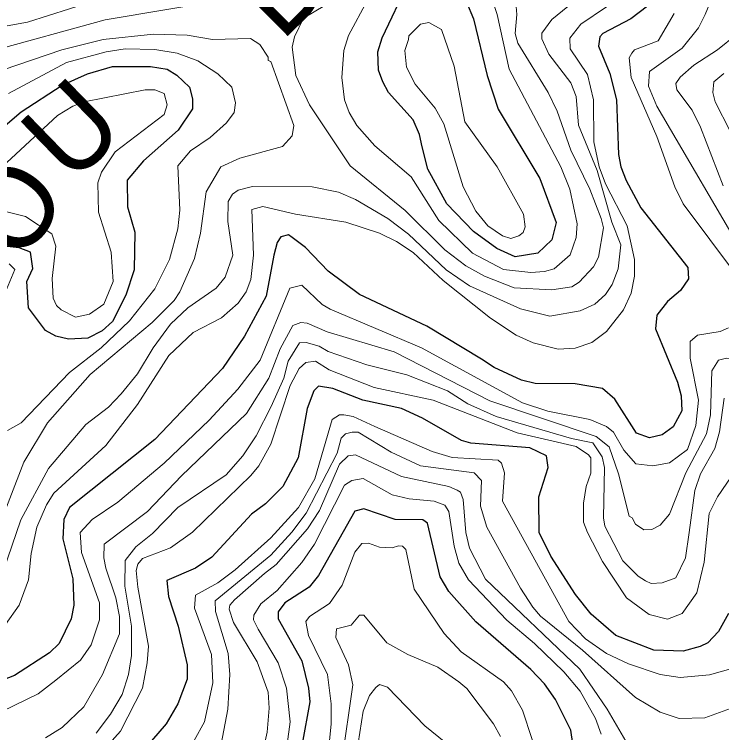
# Model space of a CAD drawing. Extents: x 423 to 448.8, y 7456.3 to 7484.
# Drawn here: x 426.689 to 427.73, y 7460.162 to 7461.22 of the extents above; entities that cross this region are included whole.
import ezdxf
from ezdxf.enums import TextEntityAlignment as Align

# ---------------------------------------------------------------- set-up
doc = ezdxf.new("R2010")
doc.units = 0
doc.header["$LTSCALE"] = 0.032
doc.layers.add('1', color=7, linetype='Continuous', lineweight=25)
doc.layers.add('2', color=7, linetype='Continuous', lineweight=13)
doc.layers.add('61', color=7, linetype='Continuous')

msp = doc.modelspace()

# ---------------------------------------------------------------- linework, layer by layer
at = {"layer": '1'}
for points in [[(427.3438, 7461.2624), (427.3646, 7461.2129), (427.3848, 7461.1294), (427.401, 7461.0799), (427.4621, 7460.9778), (427.4861, 7460.9128), (427.4799, 7460.8873), (427.459, 7460.8679), (427.4258, 7460.8625), (427.3987, 7460.8749), (427.3647, 7460.8996), (427.3252, 7460.9406), (427.2974, 7460.9917), (427.2888, 7461.0242), (427.285, 7461.0427), (427.2757, 7461.0644), (427.2393, 7461.1046), (427.2309, 7461.1201), (427.2247, 7461.1371), (427.2239, 7461.1641), (427.2301, 7461.1851), (427.2687, 7461.267)], [(427.6207, 7461.2315), (427.5959, 7461.2129), (427.5549, 7461.1912), (427.5503, 7461.1866), (427.5487, 7461.1727), (427.565, 7461.1325), (427.5751, 7461.0938), (427.5781, 7461.0133), (427.5812, 7460.9948), (427.589, 7460.9747), (427.6106, 7460.9345), (427.6802, 7460.847), (427.681, 7460.83), (427.6694, 7460.813), (427.6501, 7460.7968), (427.6346, 7460.7767), (427.6323, 7460.7566), (427.6648, 7460.6777), (427.6702, 7460.6576), (427.671, 7460.6359), (427.6586, 7460.6119), (427.6424, 7460.6003), (427.6237, 7460.5957), (427.6044, 7460.6026), (427.5727, 7460.6529), (427.5542, 7460.6684), (427.514, 7460.6753), (427.4552, 7460.6761), (427.4351, 7460.6807), (427.3949, 7460.6993), (427.3763, 7460.7117), (427.2958, 7460.7604), (427.1968, 7460.8068), (427.1504, 7460.8416), (427.1172, 7460.8764), (427.0978, 7460.8911), (427.0924, 7460.895), (427.0808, 7460.8919), (427.0754, 7460.8834), (427.0708, 7460.8648), (427.0592, 7460.8045), (427.0274, 7460.7457), (426.995, 7460.6978), (426.8952, 7460.5933), (426.7699, 7460.4936), (426.7614, 7460.4758), (426.7598, 7460.4472), (426.7745, 7460.3884), (426.7761, 7460.3497), (426.7722, 7460.3296), (426.7544, 7460.2932), (426.7405, 7460.2793), (426.6887, 7460.2461), (426.4767, 7460.1641)], [(426.6539, 7461.0381), (426.6987, 7461.076), (426.7591, 7461.1154), (426.7962, 7461.1317), (426.8333, 7461.1425), (426.889, 7461.1425), (426.9137, 7461.1386), (426.9277, 7461.1301), (426.9462, 7461.1123), (426.9509, 7461.0953), (426.9509, 7461.0806), (426.93, 7461.0489), (426.8789, 7461.004), (426.8549, 7460.9754), (426.855, 7460.936), (426.8658, 7460.8989), (426.865, 7460.8432), (426.8526, 7460.8061), (426.8333, 7460.7673), (426.8178, 7460.7535), (426.797, 7460.7426), (426.7683, 7460.7411), (426.7498, 7460.7457), (426.7343, 7460.7542), (426.7095, 7460.7875), (426.7072, 7460.8262), (426.7157, 7460.8455), (426.7126, 7460.8695), (426.6956, 7460.8757), (426.6338, 7460.8826)], [(427.3469, 7460.5918), (427.2896, 7460.625), (427.2587, 7460.639), (427.2015, 7460.6513), (427.1574, 7460.6684), (427.1365, 7460.6722), (427.1295, 7460.6653), (427.1195, 7460.639), (427.1063, 7460.5663), (427.0839, 7460.5245), (427.0584, 7460.499), (427.0375, 7460.4835), (426.9795, 7460.4201), (426.9555, 7460.4038), (426.913, 7460.3861), (426.9153, 7460.3621), (426.93, 7460.3188), (426.9431, 7460.2615), (426.9431, 7460.2406), (426.9292, 7460.2043), (426.9122, 7460.1749), (426.8596, 7460.1138)], [(427.7398, 7460.3373), (427.7251, 7460.311), (427.7096, 7460.294), (427.698, 7460.2886), (427.6733, 7460.2816), (427.63, 7460.2832), (427.5742, 7460.3048), (427.5379, 7460.3365), (427.5147, 7460.3652), (427.4784, 7460.4216), (427.4613, 7460.4564), (427.4606, 7460.5091), (427.4745, 7460.5524), (427.4722, 7460.5694), (427.4474, 7460.581), (427.3608, 7460.5879), (427.3469, 7460.5918)], [(427.5109, 7460.1455), (427.5078, 7460.1656), (427.4853, 7460.2105), (427.4691, 7460.2337), (427.449, 7460.2546), (427.3678, 7460.325), (427.3283, 7460.3698), (427.3152, 7460.3915), (427.2966, 7460.4703), (427.2897, 7460.475), (427.2494, 7460.4758), (427.203, 7460.4912), (427.1899, 7460.4881), (427.1365, 7460.393), (427.1226, 7460.376), (427.087, 7460.3528), (427.0769, 7460.3396), (427.0769, 7460.3296), (427.1118, 7460.2677), (427.1218, 7460.2275), (427.1234, 7460.2074), (427.1009, 7460.0837)]]:
    msp.add_lwpolyline(points, dxfattribs=at)
at = {"layer": '2'}
for points in [[(427.3786, 7461.281), (427.3995, 7461.2191), (427.4172, 7461.1387), (427.4931, 7460.9948), (427.5062, 7460.9623), (427.5171, 7460.9113), (427.5155, 7460.8911), (427.507, 7460.8656), (427.483, 7460.8447), (427.4691, 7460.8408), (427.449, 7460.8393), (427.4088, 7460.8439), (427.3631, 7460.8679), (427.3136, 7460.9158), (427.2726, 7460.9801), (427.2192, 7461.0257), (427.1929, 7461.0559), (427.1813, 7461.0752), (427.1744, 7461.0938), (427.1705, 7461.1263), (427.1736, 7461.1665), (427.1806, 7461.1882), (427.2084, 7461.2407)], [(427.1744, 7461.25), (427.1141, 7461.2137), (427.1009, 7461.1866), (427.0978, 7461.1711), (427.1032, 7461.1294), (427.1233, 7461.0861), (427.1829, 7460.9963), (427.2641, 7460.9306), (427.3221, 7460.8726), (427.3531, 7460.8493), (427.3809, 7460.8339), (427.4242, 7460.8169), (427.4799, 7460.8138), (427.5093, 7460.8184), (427.5201, 7460.8254), (427.541, 7460.8478), (427.5487, 7460.8618), (427.5557, 7460.9051), (427.5526, 7460.919), (427.5356, 7460.9623), (427.5078, 7461.0195), (427.4876, 7461.0768), (427.4745, 7461.1046), (427.4296, 7461.1773), (427.4257, 7461.1912), (427.4281, 7461.2191), (427.4242, 7461.267)], [(426.6585, 7460.3605), (426.698, 7460.475), (426.7389, 7460.5508), (426.7939, 7460.6158), (426.8271, 7460.6413), (426.8457, 7460.6606), (426.8697, 7460.69), (426.8928, 7460.7287), (426.9184, 7460.7635), (426.9439, 7460.7875), (426.9857, 7460.8161), (426.9988, 7460.8324), (427.0104, 7460.8648), (427.0027, 7460.9143), (427.0034, 7460.9437), (427.0097, 7460.9545), (427.0181, 7460.9607), (427.0391, 7460.9661), (427.1272, 7460.9654), (427.1659, 7460.9576), (427.1907, 7460.9468), (427.2386, 7460.919), (427.2688, 7460.8957), (427.3244, 7460.8431), (427.3585, 7460.82), (427.4335, 7460.7859), (427.4768, 7460.7751), (427.5217, 7460.7829), (427.5433, 7460.7929), (427.5588, 7460.8068), (427.5688, 7460.8215), (427.5774, 7460.8447), (427.5812, 7460.8803), (427.5681, 7460.9135), (427.5463, 7460.9894), (427.5193, 7461.0561), (427.5155, 7461.0984), (427.5078, 7461.1185), (427.4753, 7461.1611), (427.4652, 7461.1835), (427.4652, 7461.192), (427.4799, 7461.2121), (427.5403, 7461.2616)], [(427.7151, 7460.6946), (427.7251, 7460.7101), (427.7367, 7460.7132), (427.7522, 7460.7124), (427.8094, 7460.7047), (427.8976, 7460.7001), (427.9123, 7460.7055), (427.9239, 7460.7264), (427.927, 7460.741), (427.9007, 7460.7588), (427.8589, 7460.7728), (427.845, 7460.7805), (427.8148, 7460.7991), (427.7994, 7460.813), (427.7684, 7460.8556), (427.6346, 7461.0845), (427.6222, 7461.1139), (427.6238, 7461.1355), (427.6718, 7461.1696), (427.6957, 7461.1997), (427.7057, 7461.2191), (427.7174, 7461.2485)], [(426.6477, 7461.1974), (426.708, 7461.2082), (426.8008, 7461.2376)], [(427.0066, 7461.243), (426.8225, 7461.2113), (426.6508, 7461.1641)], [(427.5604, 7461.2307), (427.5225, 7461.2052), (427.5062, 7461.1843), (427.507, 7461.1688), (427.5325, 7461.1309), (427.541, 7461.0938), (427.5418, 7461.0319), (427.5495, 7460.9948), (427.5588, 7460.97), (427.5905, 7460.9082), (427.6013, 7460.8587), (427.6013, 7460.8339), (427.5967, 7460.8092), (427.5851, 7460.7844), (427.5604, 7460.7527), (427.5387, 7460.7364), (427.514, 7460.7279), (427.4892, 7460.7264), (427.4521, 7460.7356), (427.4273, 7460.7472), (427.3894, 7460.772), (427.3198, 7460.8277), (427.2757, 7460.8687), (427.251, 7460.8849), (427.2262, 7460.8973)], [(427.6601, 7461.2206), (427.6361, 7461.1804), (427.6013, 7461.1672), (427.5975, 7461.1626), (427.5936, 7461.1557), (427.5967, 7461.1263), (427.6346, 7461.0396), (427.6609, 7460.9654), (427.6733, 7460.9406), (427.7514, 7460.8355)], [(426.6724, 7461.1378), (426.7583, 7461.1672), (426.8194, 7461.1827), (426.8936, 7461.1904), (426.9432, 7461.1889), (426.9803, 7461.1827), (427.036, 7461.1842), (427.0499, 7461.175), (427.0623, 7461.1564), (427.0623, 7461.1518), (427.0661, 7461.1502), (427.1001, 7461.0559), (427.0978, 7461.0404), (427.0831, 7461.0249), (427.0205, 7461.0079), (426.9926, 7460.9948), (426.971, 7460.9584), (426.9625, 7460.8973), (426.954, 7460.8602), (426.9323, 7460.8107), (426.9238, 7460.7983), (426.8913, 7460.7658), (426.8, 7460.6892), (426.7374, 7460.6181), (426.7026, 7460.5601), (426.6631, 7460.4596)], [(427.7514, 7461.1897), (427.7235, 7461.1672), (427.6887, 7461.1448), (427.6687, 7461.127), (427.6625, 7461.1178), (427.664, 7461.1085), (427.6864, 7461.0783), (427.6988, 7461.0536), (427.732, 7460.9669)], [(426.6786, 7460.6065), (426.6987, 7460.6181), (426.7699, 7460.6923), (426.8163, 7460.7287), (426.8581, 7460.7681), (426.8952, 7460.8153), (426.9168, 7460.8587), (426.9292, 7460.9035), (426.9323, 7460.9314), (426.9292, 7460.9963), (426.9478, 7461.0187), (426.9771, 7461.0381), (427.0011, 7461.0597), (427.012, 7461.0752), (427.0143, 7461.0891), (427.0089, 7461.1123), (426.988, 7461.1317), (426.9586, 7461.151), (426.9284, 7461.1626), (426.8952, 7461.168), (426.8519, 7461.1688), (426.824, 7461.1641), (426.7653, 7461.1487), (426.6802, 7461.103)], [(427.7421, 7461.0474), (427.7204, 7461.0907), (427.7166, 7461.1046), (427.7181, 7461.1201), (427.7328, 7461.1325)], [(426.6631, 7460.9886), (426.7521, 7461.0705), (426.7745, 7461.0845), (426.7916, 7461.0907), (426.8813, 7461.1085), (426.8952, 7461.1085), (426.9091, 7461.103), (426.9138, 7461.0861), (426.9091, 7461.0721), (426.8372, 7461.0172), (426.817, 7460.9871), (426.8117, 7460.9716), (426.8124, 7460.9283), (426.831, 7460.8695), (426.8341, 7460.8262), (426.8201, 7460.7929), (426.7993, 7460.7782), (426.7784, 7460.7735), (426.7575, 7460.7844), (426.7505, 7460.7906), (426.7459, 7460.8014), (426.7443, 7460.8308), (426.7497, 7460.878), (426.7436, 7460.8965), (426.7049, 7460.922), (426.6616, 7460.9329)], [(427.2262, 7460.8973), (427.1767, 7460.9135), (427.1025, 7460.9252), (427.0545, 7460.9367), (427.0383, 7460.9321), (427.0406, 7460.8648), (427.0367, 7460.8293), (427.0297, 7460.8107), (427.0182, 7460.7944), (426.9934, 7460.7728), (426.9516, 7460.7511), (426.916, 7460.7171), (426.8697, 7460.6452), (426.8232, 7460.5848), (426.7467, 7460.5144), (426.7358, 7460.4974), (426.7219, 7460.4642), (426.7134, 7460.4255), (426.7096, 7460.3868), (426.6956, 7460.3497), (426.6755, 7460.3211)], [(426.6809, 7460.8524), (426.6894, 7460.8439), (426.6771, 7460.8145)], [(427.0939, 7460.8161), (427.0506, 7460.7102), (427.0174, 7460.6676), (426.9756, 7460.6219), (426.9091, 7460.5585), (426.8411, 7460.5013), (426.8031, 7460.4758), (426.7854, 7460.4564), (426.7877, 7460.4271), (426.814, 7460.3528), (426.814, 7460.3281), (426.8016, 7460.2909), (426.7861, 7460.2685), (426.7498, 7460.2391), (426.7235, 7460.219), (426.6152, 7460.1664)], [(427.7398, 7460.7581), (427.7274, 7460.7527), (427.6941, 7460.7473), (427.6833, 7460.738), (427.6833, 7460.7132), (427.6957, 7460.6514), (427.6919, 7460.6142), (427.6795, 7460.5786), (427.6532, 7460.5593), (427.6284, 7460.5547), (427.6037, 7460.5578), (427.5859, 7460.5779), (427.5704, 7460.6042), (427.5604, 7460.6127), (427.5356, 7460.6227), (427.4737, 7460.6351), (427.4366, 7460.6475), (427.2881, 7460.7287), (427.1535, 7460.7852), (427.1419, 7460.7921), (427.1117, 7460.8207), (427.0939, 7460.8161)], [(426.7343, 7460.154), (426.7591, 7460.1695), (426.7907, 7460.1996), (426.8186, 7460.2476), (426.8433, 7460.3072), (426.8433, 7460.3327), (426.8379, 7460.3605), (426.8232, 7460.4039), (426.8201, 7460.4193), (426.8209, 7460.4394), (426.8844, 7460.4874), (426.9346, 7460.5399), (427.0305, 7460.632), (427.063, 7460.6839), (427.08, 7460.7272), (427.0986, 7460.7612), (427.1102, 7460.7658), (427.1195, 7460.765), (427.1489, 7460.7519), (427.2479, 7460.7225), (427.3887, 7460.6506), (427.5449, 7460.598), (427.5642, 7460.5825), (427.5781, 7460.5431), (427.5936, 7460.4804), (427.5983, 7460.4781), (427.6029, 7460.4688), (427.6153, 7460.4603), (427.6269, 7460.4611), (427.6392, 7460.4672), (427.6531, 7460.4835), (427.6771, 7460.5446), (427.7073, 7460.6019), (427.7135, 7460.6297), (427.7151, 7460.6946)], [(427.7336, 7460.6545), (427.7266, 7460.605), (427.7197, 7460.5802), (427.6988, 7460.5431), (427.6903, 7460.5183), (427.6818, 7460.4565), (427.6764, 7460.4193), (427.6624, 7460.3899), (427.6424, 7460.3822), (427.6261, 7460.3814), (427.6176, 7460.3853), (427.6067, 7460.3922), (427.5843, 7460.4147), (427.558, 7460.4657), (427.5557, 7460.4781), (427.5572, 7460.5524), (427.5541, 7460.5678), (427.5403, 7460.5887), (427.5088, 7460.5948), (427.3979, 7460.6274), (427.3561, 7460.6459), (427.326, 7460.6653), (427.2665, 7460.6885), (427.2077, 7460.7032), (427.1504, 7460.7233), (427.1373, 7460.731), (427.118, 7460.7364), (427.1086, 7460.7357), (427.0916, 7460.7086), (427.0854, 7460.6839), (427.0669, 7460.6421), (427.0445, 7460.5988), (427.0251, 7460.5694), (427.0003, 7460.5415), (426.9292, 7460.4935), (426.8921, 7460.4549), (426.8674, 7460.4355), (426.8519, 7460.4154), (426.8511, 7460.3776), (426.8612, 7460.3188), (426.8612, 7460.2755), (426.8565, 7460.2476), (426.8472, 7460.2182), (426.8302, 7460.1888), (426.8093, 7460.161)], [(426.8681, 7460.4008), (426.8704, 7460.4101), (426.8774, 7460.4185), (426.9184, 7460.434), (426.9509, 7460.4572), (427.0367, 7460.5407), (427.0483, 7460.5547), (427.0661, 7460.5864), (427.0947, 7460.673), (427.1079, 7460.6978), (427.1179, 7460.7071), (427.1319, 7460.7086), (427.1519, 7460.6962), (427.2185, 7460.6699), (427.3051, 7460.6513), (427.4289, 7460.6034), (427.5155, 7460.5833), (427.534, 7460.5709), (427.5372, 7460.5663), (427.5372, 7460.5438), (427.5302, 7460.5245), (427.5263, 7460.4998), (427.5263, 7460.4719), (427.5325, 7460.4565), (427.5542, 7460.4139), (427.5898, 7460.3605), (427.623, 7460.3358), (427.6501, 7460.3288), (427.6717, 7460.3373), (427.6934, 7460.3675), (427.7042, 7460.4131), (427.7112, 7460.4843), (427.7235, 7460.5091), (427.7584, 7460.5601)], [(427.6393, 7460.2476), (427.5929, 7460.2631), (427.5604, 7460.2785), (427.5294, 7460.3002), (427.5046, 7460.3257), (427.4072, 7460.5029), (427.4103, 7460.5446), (427.4057, 7460.5586), (427.401, 7460.5632), (427.333, 7460.567), (427.3036, 7460.5756), (427.2192, 7460.6127), (427.1876, 7460.6274), (427.1736, 7460.6297), (427.1674, 7460.6297), (427.1566, 7460.6227), (427.1311, 7460.5354), (427.1071, 7460.4936), (427.0661, 7460.4487), (427.0135, 7460.4015), (426.988, 7460.3822), (426.9555, 7460.3644), (426.954, 7460.3451), (426.9787, 7460.277), (426.981, 7460.2352), (426.9686, 7460.178), (426.9532, 7460.1502)], [(427.7429, 7460.1973), (427.705, 7460.1834), (427.6671, 7460.1826), (427.6393, 7460.1919), (427.6029, 7460.2136), (427.5248, 7460.2832), (427.4629, 7460.3335), (427.452, 7460.3466), (427.4335, 7460.3745), (427.384, 7460.4642), (427.3747, 7460.4951), (427.3763, 7460.533), (427.3655, 7460.5446), (427.2866, 7460.5547), (427.2433, 7460.5748), (427.1945, 7460.6042), (427.186, 7460.6042), (427.1759, 7460.6019), (427.1697, 7460.5956), (427.1638, 7460.5736), (427.118, 7460.485), (427.097, 7460.4572)], [(427.599, 7460.1316), (427.5611, 7460.1965), (427.5209, 7460.2554), (427.3824, 7460.3876), (427.3585, 7460.4333), (427.353, 7460.4565), (427.3492, 7460.5052), (427.3453, 7460.516), (427.3407, 7460.5191), (427.3283, 7460.5245), (427.2587, 7460.5392), (427.1907, 7460.5709), (427.1798, 7460.5693), (427.1674, 7460.557), (427.138, 7460.4889), (427.1202, 7460.4619), (427.0738, 7460.4093), (427.0568, 7460.3961), (427.0127, 7460.3575), (427.0058, 7460.3497), (427.005, 7460.3435), (427.0112, 7460.3242), (427.046, 7460.2662), (427.0622, 7460.2213), (427.0638, 7460.1981), (427.0607, 7460.1625), (427.0529, 7460.127)], [(427.5441, 7460.1827), (427.5217, 7460.2229), (427.4977, 7460.2515), (427.4544, 7460.2932), (427.4134, 7460.3273), (427.3569, 7460.3868), (427.343, 7460.4116), (427.3361, 7460.4363), (427.3283, 7460.4874), (427.3221, 7460.4967), (427.3067, 7460.5029), (427.2696, 7460.506), (427.2448, 7460.5121), (427.2022, 7460.5361), (427.1852, 7460.533), (427.1744, 7460.5261), (427.1303, 7460.4394), (427.1118, 7460.4124), (427.0754, 7460.3713), (427.0514, 7460.3513), (427.0413, 7460.335), (427.0406, 7460.328), (427.0475, 7460.3141), (427.0769, 7460.2646), (427.0893, 7460.2275), (427.0947, 7460.178), (427.087, 7460.1192)], [(427.097, 7460.4572), (427.0661, 7460.4232), (426.9841, 7460.3559), (426.9849, 7460.3404), (427.0035, 7460.2786), (427.0058, 7460.2476), (427.0027, 7460.1966), (426.9911, 7460.1347)], [(427.1504, 7460.1301), (427.1551, 7460.1749), (427.1551, 7460.2043), (427.1496, 7460.2476), (427.1218, 7460.3049), (427.1179, 7460.3257), (427.1233, 7460.3327), (427.1527, 7460.352), (427.1713, 7460.3791), (427.1898, 7460.4278), (427.1999, 7460.4402), (427.21, 7460.441), (427.2262, 7460.4348), (427.2448, 7460.434), (427.2541, 7460.4371), (427.2602, 7460.4363), (427.2649, 7460.4317), (427.2772, 7460.3729), (427.3213, 7460.308), (427.3461, 7460.2809), (427.4088, 7460.2368), (427.4204, 7460.2236), (427.4366, 7460.195), (427.4652, 7460.1084)], [(426.6585, 7460.0496), (426.7328, 7460.0712), (426.7761, 7460.0944), (426.7954, 7460.1084), (426.8449, 7460.1641), (426.8774, 7460.2275), (426.8843, 7460.2646), (426.8859, 7460.2894), (426.8704, 7460.376), (426.8681, 7460.4008)], [(427.4041, 7460.1564), (427.394, 7460.1749), (427.3546, 7460.2267), (427.343, 7460.2368), (427.3121, 7460.2584), (427.268, 7460.277), (427.2371, 7460.294), (427.203, 7460.335), (427.1968, 7460.335), (427.1844, 7460.3203), (427.1628, 7460.3149), (427.162, 7460.3017), (427.1806, 7460.2615)], [(427.1806, 7460.2615), (427.1868, 7460.2322), (427.1705, 7460.1192)], [(427.7661, 7460.2623), (427.712, 7460.2468), (427.6687, 7460.243), (427.6393, 7460.2476)], [(427.3446, 7460.13), (427.2927, 7460.1718), (427.2378, 7460.229), (427.2259, 7460.2328), (427.2208, 7460.2283), (427.2115, 7460.2167), (427.2022, 7460.1935), (427.1875, 7460.0991)], [(427.5526, 7460.1594), (427.5441, 7460.1827)]]:
    msp.add_lwpolyline(points, dxfattribs=at)
msp.add_lwpolyline([(427.2687, 7461.1827), (427.2695, 7461.1881), (427.2865, 7461.2052), (427.2989, 7461.2075), (427.3175, 7461.1974), (427.3361, 7461.1433), (427.3515, 7461.0613), (427.3995, 7460.9948), (427.4381, 7460.9252), (427.4405, 7460.9066), (427.4374, 7460.8981), (427.4312, 7460.8934), (427.4196, 7460.8896), (427.4072, 7460.8934), (427.3856, 7460.9082), (427.3677, 7460.9298), (427.3492, 7460.9654), (427.3206, 7461.0582), (427.3082, 7461.0814), (427.2788, 7461.1169), (427.2657, 7461.1417), (427.2634, 7461.1665)], close=True, dxfattribs=at)

# ---------------------------------------------------------------- texts
at = {"layer": '61'}
for s, rotation, p in [('D', 44.815, (427.1229, 7461.219)), ('U', 44.142, (426.8144, 7461.0071)), ('O', 54.731, (426.7348, 7460.9009))]:
    msp.add_text(s, height=0.12, rotation=rotation, dxfattribs=at).set_placement(p, align=Align.CENTER)

doc.saveas('drawing.dxf')
